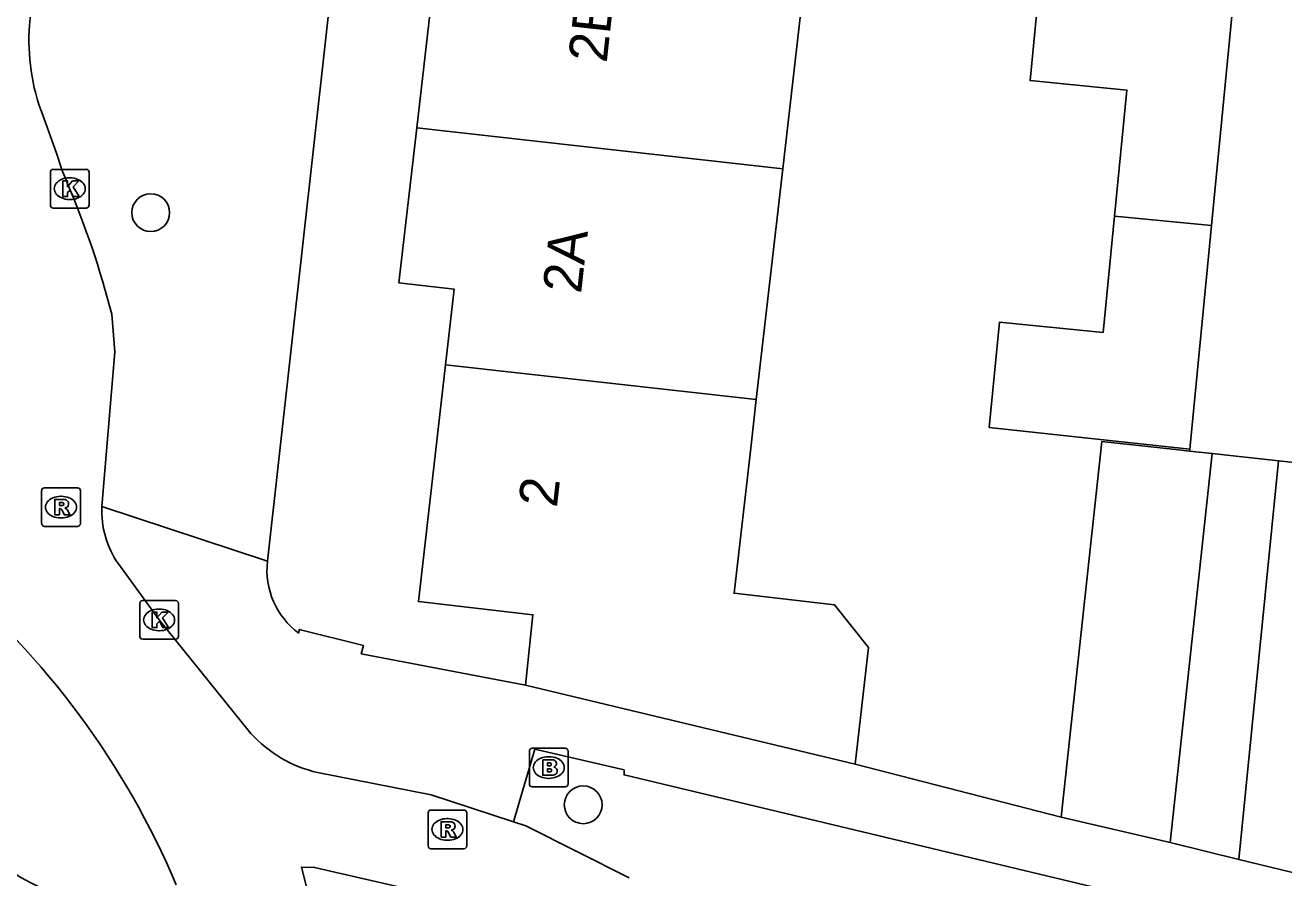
# Model space of a CAD drawing. Extents: x 162026 to 163499, y 387297 to 388169.
# Drawn here: x 162364.87 to 162397.42, y 387408.21 to 387430.26 of the extents above; entities that cross this region are included whole.
import ezdxf

# ---------------------------------------------------------------- set-up
doc = ezdxf.new("R2010")
doc.units = 0
for name, color, linetype in [('IMGEO_Boom', 7, 'Continuous'), ('IMGEO_Brandkraan', 7, 'Continuous'), ('IMGEO_Fietspad_gesloten', 7, 'Continuous'), ('IMGEO_Kolk', 7, 'Continuous'), ('IMGEO_Muur', 7, 'Continuous'), ('IMGEO_Pand', 7, 'Continuous'), ('IMGEO_Pand_nummerreeks', 7, 'Continuous'), ('IMGEO_Rijbaan_lokaal_gesloten', 7, 'Continuous'), ('IMGEO_Rijbaan_lokaal_open', 7, 'Continuous'), ('IMGEO_Rioolput', 7, 'Continuous'), ('IMGEO_Voetpad_open', 7, 'Continuous')]:
    doc.layers.add(name, color=color, linetype=linetype)

msp = doc.modelspace()

# ---------------------------------------------------------------- linework, layer by layer
at = {"layer": 'IMGEO_Boom'}
for centre in [(162368.117, 387425.414), (162379.301, 387410.098)]:
    msp.add_circle(centre, 0.489, dxfattribs=at)
at = {"layer": 'IMGEO_Brandkraan'}
for p, q in [((162377.908, 387410.636), (162377.908, 387411.488)), ((162377.983, 387411.562), (162378.835, 387411.562)), ((162378.909, 387411.488), (162378.909, 387410.636)), ((162378.396, 387411.342), (162378.421, 387411.342)), ((162378.419, 387410.782), (162378.394, 387410.782)), ((162378.835, 387410.562), (162377.983, 387410.562))]:
    msp.add_line(p, q, dxfattribs=at)
for points in [[(162377.908, 387410.636), (162377.908, 387411.488)], [(162377.983, 387411.562), (162378.835, 387411.562)], [(162378.909, 387411.488), (162378.909, 387410.636)], [(162378.256, 387411.262), (162378.256, 387410.862), (162378.469, 387410.862)], [(162378.487, 387411.262), (162378.256, 387411.262)], [(162378.435, 387411.181), (162378.381, 387411.181), (162378.381, 387411.105)], [(162378.381, 387411.105), (162378.434, 387411.105)], [(162378.443, 387411.029), (162378.381, 387411.029), (162378.381, 387410.948)], [(162378.381, 387410.948), (162378.443, 387410.948)], [(162378.835, 387410.562), (162377.983, 387410.562)]]:
    msp.add_lwpolyline(points, dxfattribs=at)
for centre, radius, start, end in [((162377.985, 387411.486), 0.0765, 91.552, 178.448), ((162377.985, 387411.486), 0.0765, 91.552, 178.448), ((162378.833, 387411.486), 0.0765, 1.552, 88.448), ((162378.833, 387411.486), 0.0765, 1.552, 88.448), ((162378.436, 387411.143), 0.0379, 267.8285, 90.9355), ((162378.444, 387410.988), 0.0404, 269.8759, 90.5077), ((162378.491, 387411.117), 0.145, 59.4692, 91.5367), ((162378.516, 387411.164), 0.0922, 285.5137, 58.1501), ((162378.521, 387410.972), 0.105, 301.3115, 78.989), ((162378.475, 387411.113), 0.251, 268.6676, 293.5347), ((162377.985, 387410.638), 0.0765, 181.552, 268.448), ((162377.985, 387410.638), 0.0765, 181.552, 268.448), ((162378.833, 387410.638), 0.0765, 271.552, 358.448), ((162378.833, 387410.638), 0.0765, 271.552, 358.448)]:
    msp.add_arc(centre, radius, start, end, dxfattribs=at)
for centre, major_axis, ratio, start_param, end_param in [((162378.395, 387411.062), (-0.387, 0.002), 0.722429, 4.712389, 7.853982), ((162378.42, 387411.062), (-0.39, 0.002), 0.717154, 1.570796, 4.712389)]:
    msp.add_ellipse(centre, major_axis=major_axis, ratio=ratio, start_param=start_param, end_param=end_param, dxfattribs=at)
at = {"layer": 'IMGEO_Fietspad_gesloten'}
for points in [[(162365.039, 387430.868), (162364.983, 387430.263)], [(162365.325, 387427.933), (162365.683, 387426.954)], [(162365.9, 387426.321), (162365.928, 387426.252), (162365.958, 387426.183)], [(162367.108, 387422.786), (162367.19, 387421.816), (162366.853, 387417.815)], [(162370.708, 387411.942), (162368.334, 387414.881), (162367.279, 387416.327)], [(162377.495, 387409.656), (162375.368, 387410.356), (162372.429, 387410.931)], [(162377.495, 387409.656), (162377.814, 387409.551), (162380.493, 387408.209)], [(162377.345, 387407.089), (162375.28, 387407.8), (162372.355, 387408.478), (162372.014, 387408.489), (162372.573, 387406.278)]]:
    msp.add_lwpolyline(points, dxfattribs=at)
for centre, radius, start, end in [((162370.276, 387429.85), 5.309, 175.5359, 201.1647), ((162371.018, 387428.429), 5.535, 195.4568, 202.3879), ((162344.425, 387417), 23.409, 14.3094, 23.096), ((162369.256, 387417.698), 2.406, 177.2096, 214.7422), ((162349.148, 387399.739), 21.306, 22.8824, 50.1851), ((162373.198, 387414.21), 3.368, 222.3301, 256.8058)]:
    msp.add_arc(centre, radius, start, end, dxfattribs=at)
at = {"layer": 'IMGEO_Kolk'}
for p, q in [((162365.521, 387425.608), (162365.521, 387426.46)), ((162365.596, 387426.534), (162366.448, 387426.534)), ((162366.522, 387426.46), (162366.522, 387425.608)), ((162366.009, 387426.314), (162366.034, 387426.314)), ((162366.032, 387425.754), (162366.007, 387425.754)), ((162366.448, 387425.534), (162365.596, 387425.534)), ((162367.833, 387414.455), (162367.833, 387415.307)), ((162367.908, 387415.381), (162368.76, 387415.381)), ((162368.834, 387415.307), (162368.834, 387414.455)), ((162368.321, 387415.161), (162368.346, 387415.161)), ((162368.344, 387414.601), (162368.319, 387414.601)), ((162368.76, 387414.381), (162367.908, 387414.381))]:
    msp.add_line(p, q, dxfattribs=at)
for points in [[(162365.521, 387425.608), (162365.521, 387426.46)], [(162365.596, 387426.534), (162366.448, 387426.534)], [(162366.522, 387426.46), (162366.522, 387425.608)], [(162365.842, 387426.234), (162365.965, 387426.234), (162365.965, 387426.083), (162366.095, 387426.234), (162366.259, 387426.234), (162366.113, 387426.083), (162366.266, 387425.834), (162366.114, 387425.834), (162366.029, 387425.998), (162365.965, 387425.931), (162365.965, 387425.834), (162365.842, 387425.834), (162365.842, 387426.234)], [(162366.448, 387425.534), (162365.596, 387425.534)], [(162367.833, 387414.455), (162367.833, 387415.307)], [(162367.908, 387415.381), (162368.76, 387415.381)], [(162368.834, 387415.307), (162368.834, 387414.455)], [(162368.154, 387415.081), (162368.277, 387415.081), (162368.277, 387414.93), (162368.407, 387415.081), (162368.571, 387415.081), (162368.425, 387414.93), (162368.578, 387414.681), (162368.426, 387414.681), (162368.341, 387414.845), (162368.277, 387414.778), (162368.277, 387414.681), (162368.154, 387414.681), (162368.154, 387415.081)], [(162368.76, 387414.381), (162367.908, 387414.381)]]:
    msp.add_lwpolyline(points, dxfattribs=at)
for centre, start, end in [((162365.598, 387426.458), 91.552, 178.448), ((162365.598, 387426.458), 91.552, 178.448), ((162366.446, 387426.458), 1.552, 88.448), ((162366.446, 387426.458), 1.552, 88.448), ((162365.598, 387425.61), 181.552, 268.448), ((162365.598, 387425.61), 181.552, 268.448), ((162366.446, 387425.61), 271.552, 358.448), ((162366.446, 387425.61), 271.552, 358.448), ((162367.91, 387415.305), 91.552, 178.448), ((162367.91, 387415.305), 91.552, 178.448), ((162368.758, 387415.305), 1.552, 88.448), ((162368.758, 387415.305), 1.552, 88.448), ((162367.91, 387414.457), 181.552, 268.448), ((162367.91, 387414.457), 181.552, 268.448), ((162368.758, 387414.457), 271.552, 358.448), ((162368.758, 387414.457), 271.552, 358.448)]:
    msp.add_arc(centre, 0.0765, start, end, dxfattribs=at)
for centre, major_axis, ratio, start_param, end_param in [((162366.008, 387426.034), (-0.387, 0.002), 0.722429, 4.712389, 7.853982), ((162366.033, 387426.034), (-0.39, 0.002), 0.717154, 1.570796, 4.712389), ((162368.32, 387414.881), (-0.387, 0.002), 0.722429, 4.712389, 7.853982), ((162368.345, 387414.881), (-0.39, 0.002), 0.717154, 1.570796, 4.712389)]:
    msp.add_ellipse(centre, major_axis=major_axis, ratio=ratio, start_param=start_param, end_param=end_param, dxfattribs=at)
at = {"layer": 'IMGEO_Muur'}
msp.add_lwpolyline([(162391.662, 387409.78), (162386.331, 387411.152)], dxfattribs=at)
at = {"layer": 'IMGEO_Pand'}
for points in [[(162374.994, 387427.606), (162375.453, 387431.599), (162376.839, 387431.44), (162377.066, 387433.415)], [(162385.147, 387432.501), (162384.462, 387426.543)], [(162393.042, 387425.325), (162393.359, 387428.586), (162390.855, 387428.829), (162391.126, 387431.615)], [(162396.134, 387431.128), (162395.547, 387425.082)], [(162374.994, 387427.606), (162374.533, 387423.596), (162375.967, 387423.431), (162375.743, 387421.481)], [(162384.462, 387426.543), (162374.994, 387427.606)], [(162384.462, 387426.543), (162383.777, 387420.583)], [(162394.985, 387419.298), (162389.801, 387419.859), (162390.065, 387422.578), (162392.75, 387422.317), (162393.042, 387425.325)], [(162395.547, 387425.082), (162393.042, 387425.325)], [(162395.547, 387425.082), (162394.985, 387419.298)], [(162375.743, 387421.481), (162375.039, 387415.353), (162377.999, 387415.013), (162377.809, 387413.191)], [(162375.743, 387421.481), (162383.777, 387420.583)], [(162383.777, 387420.583), (162383.641, 387419.398), (162383.201, 387415.569), (162385.799, 387415.271), (162386.677, 387414.163), (162386.331, 387411.152)], [(162391.662, 387409.78), (162392.713, 387419.492), (162394.616, 387419.286), (162394.98, 387419.247)], [(162395.566, 387419.183), (162394.477, 387409.121)], [(162394.98, 387419.247), (162395.566, 387419.183)], [(162377.809, 387413.191), (162386.331, 387411.152)], [(162391.662, 387409.78), (162394.477, 387409.121)]]:
    msp.add_lwpolyline(points, dxfattribs=at)
at = {"layer": 'IMGEO_Rijbaan_lokaal_gesloten'}
msp.add_arc((162367.693, 387413.342), 5.905, 166.7956, 258.967, dxfattribs=at)
at = {"layer": 'IMGEO_Rijbaan_lokaal_open'}
for points in [[(162394.985, 387419.298), (162394.98, 387419.247)], [(162395.566, 387419.183), (162397.281, 387418.997)], [(162397.281, 387418.997), (162398.996, 387418.812)]]:
    msp.add_lwpolyline(points, dxfattribs=at)
at = {"layer": 'IMGEO_Rioolput'}
for p, q in [((162365.296, 387417.371), (162365.296, 387418.223)), ((162365.371, 387418.297), (162366.223, 387418.297)), ((162366.297, 387418.223), (162366.297, 387417.371)), ((162365.784, 387418.077), (162365.809, 387418.077)), ((162366.223, 387417.297), (162365.371, 387417.297)), ((162365.807, 387417.517), (162365.782, 387417.517)), ((162375.289, 387409.035), (162375.289, 387409.887)), ((162375.364, 387409.961), (162376.216, 387409.961)), ((162375.777, 387409.741), (162375.802, 387409.741)), ((162376.29, 387409.887), (162376.29, 387409.035)), ((162375.8, 387409.181), (162375.775, 387409.181)), ((162376.216, 387408.961), (162375.364, 387408.961))]:
    msp.add_line(p, q, dxfattribs=at)
for points in [[(162365.296, 387417.371), (162365.296, 387418.223)], [(162365.371, 387418.297), (162366.223, 387418.297)], [(162366.297, 387418.223), (162366.297, 387417.371)], [(162365.885, 387417.995), (162365.633, 387417.997), (162365.633, 387417.597)], [(162365.811, 387417.916), (162365.757, 387417.916), (162365.757, 387417.835)], [(162365.633, 387417.597), (162365.757, 387417.597), (162365.757, 387417.759), (162365.768, 387417.759)], [(162365.757, 387417.835), (162365.809, 387417.835)], [(162365.815, 387417.73), (162365.886, 387417.597), (162366.026, 387417.597), (162365.961, 387417.723)], [(162366.223, 387417.297), (162365.371, 387417.297)], [(162375.289, 387409.035), (162375.289, 387409.887)], [(162375.364, 387409.961), (162376.216, 387409.961)], [(162376.29, 387409.887), (162376.29, 387409.035)], [(162375.878, 387409.659), (162375.626, 387409.661), (162375.626, 387409.261)], [(162375.626, 387409.261), (162375.75, 387409.261), (162375.75, 387409.423), (162375.761, 387409.423)], [(162375.804, 387409.58), (162375.75, 387409.58), (162375.75, 387409.499)], [(162375.75, 387409.499), (162375.802, 387409.499)], [(162375.808, 387409.394), (162375.879, 387409.261), (162376.019, 387409.261), (162375.954, 387409.387)], [(162376.216, 387408.961), (162375.364, 387408.961)]]:
    msp.add_lwpolyline(points, dxfattribs=at)
for centre, radius, start, end in [((162365.373, 387418.221), 0.0765, 91.552, 178.448), ((162365.373, 387418.221), 0.0765, 91.552, 178.448), ((162366.221, 387418.221), 0.0765, 1.552, 88.448), ((162366.221, 387418.221), 0.0765, 1.552, 88.448), ((162365.817, 387417.82), 0.0964, 77.0061, 93.1865), ((162365.831, 387417.877), 0.0378, 276.6634, 79.6772), ((162365.884, 387417.885), 0.109, 350.3612, 89.416), ((162365.882, 387417.885), 0.112, 277.5842, 350.9817), ((162365.767, 387417.706), 0.0533, 26.0293, 88.6989), ((162365.793, 387418.024), 0.19, 274.7715, 282.9687), ((162365.866, 387417.67), 0.108, 29.5134, 73.7905), ((162365.373, 387417.373), 0.0765, 181.552, 268.448), ((162365.373, 387417.373), 0.0765, 181.552, 268.448), ((162366.221, 387417.373), 0.0765, 271.552, 358.448), ((162366.221, 387417.373), 0.0765, 271.552, 358.448), ((162375.366, 387409.885), 0.0765, 91.552, 178.448), ((162375.366, 387409.885), 0.0765, 91.552, 178.448), ((162376.214, 387409.885), 0.0765, 1.552, 88.448), ((162376.214, 387409.885), 0.0765, 1.552, 88.448), ((162375.76, 387409.37), 0.0533, 26.0293, 88.6989), ((162375.786, 387409.688), 0.19, 274.7715, 282.9687), ((162375.81, 387409.484), 0.0964, 77.0061, 93.1865), ((162375.824, 387409.541), 0.0378, 276.6634, 79.6772), ((162375.877, 387409.549), 0.109, 350.3612, 89.416), ((162375.875, 387409.549), 0.112, 277.5842, 350.9817), ((162375.859, 387409.334), 0.108, 29.5134, 73.7905), ((162375.366, 387409.037), 0.0765, 181.552, 268.448), ((162375.366, 387409.037), 0.0765, 181.552, 268.448), ((162376.214, 387409.037), 0.0765, 271.552, 358.448), ((162376.214, 387409.037), 0.0765, 271.552, 358.448)]:
    msp.add_arc(centre, radius, start, end, dxfattribs=at)
for centre, major_axis, ratio, start_param, end_param in [((162365.783, 387417.797), (-0.387, 0.002), 0.722429, 4.712389, 7.853982), ((162365.808, 387417.797), (-0.39, 0.002), 0.717154, 1.570796, 4.712389), ((162375.776, 387409.461), (-0.387, 0.002), 0.722429, 4.712389, 7.853982), ((162375.801, 387409.461), (-0.39, 0.002), 0.717154, 1.570796, 4.712389)]:
    msp.add_ellipse(centre, major_axis=major_axis, ratio=ratio, start_param=start_param, end_param=end_param, dxfattribs=at)
at = {"layer": 'IMGEO_Voetpad_open'}
for points in [[(162371.134, 387416.396), (162375.655, 387456.942), (162376.03, 387460.239), (162376.131, 387460.234)], [(162397.281, 387418.997), (162396.253, 387408.686)], [(162366.853, 387417.815), (162371.134, 387416.396)], [(162371.947, 387414.533), (162371.957, 387414.634), (162373.616, 387414.217), (162373.56, 387414.003), (162377.809, 387413.191)], [(162390.026, 387404.153), (162390.673, 387406.855), (162396.508, 387405.474), (162396.863, 387406.924), (162380.357, 387410.869), (162380.357, 387410.999), (162378.049, 387411.538), (162377.495, 387409.656)], [(162386.331, 387411.152), (162391.662, 387409.78)], [(162394.477, 387409.121), (162396.253, 387408.686)], [(162396.253, 387408.686), (162397.856, 387408.293)]]:
    msp.add_lwpolyline(points, dxfattribs=at)
msp.add_arc((162373.162, 387416.172), 2.04, 173.6926, 233.4596, dxfattribs=at)

# ---------------------------------------------------------------- texts
at = {"layer": 'IMGEO_Pand_nummerreeks'}
for s, rotation, p in [('2B', 83.6731, (162379.906, 387429.271)), ('2A', 83.6659, (162379.244, 387423.303)), ('2', 83.4557, (162378.618, 387417.767))]:
    msp.add_text(s, height=1, rotation=rotation, dxfattribs=at).set_placement(p)

doc.saveas('drawing.dxf')
